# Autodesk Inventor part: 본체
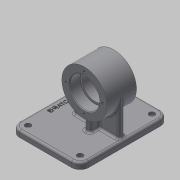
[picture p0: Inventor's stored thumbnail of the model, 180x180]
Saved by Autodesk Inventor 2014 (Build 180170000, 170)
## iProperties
Created: 2019-09
Part Number: 본체
Material: Generic
Document SubType Name: Modeling
Designer: kh
Density: 1 g/cm^3
Appearance: Default
Author: kh
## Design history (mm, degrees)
sketch "Sketch1"
  geometry: L1 (-51, -49)-(51, -49); L2 (63, -37)-(63, 37); L3 (51, 49)-(-51, 49); L4 (-63, 37)-(-63, -37); L5 (-63, -49)-(63, 49); L6 (63, -49)-(-63, 49); A1 r 12 centre (-51, 37) between (-51, 49) and (-63, 37); A2 r 12 centre (-51, -37) between (-63, -37) and (-51, -49); A3 r 12 centre (51, -37) between (51, -49) and (63, -37); A4 r 12 centre (51, 37) between (63, 37) and (51, 49); 1 further point
  constraints: 12 end point, 8 point on circle, 8 point on line, 8 tangent, 4 centre point, 3 equal radius, 2 midpoint, 2 parallel, 1 horizontal, 1 perpendicular
  dimensions: "d0" = 126 distance of L5.end L6.end; "d1" = 98 distance of L6.end L5.start; "d2" = 12 radius of A1
extrude "Extrusion1" new body sketch "Sketch1" distance "d3" = 9; taper "d4" = 0 deg
sketch "Sketch2"
  geometry: A1 r 12 centre (-51, 37) between (-51, 49) and (-63, 37) reference; A2 r 12 centre (51, 37) between (63, 37) and (51, 49) reference; A3 r 12 centre (51, -37) between (51, -49) and (63, -37) reference; A4 r 12 centre (-51, -37) between (-63, -37) and (-51, -49) reference; 5 further points
  constraints: 4 coincident
hole "Hole1" sketch "Sketch2" at (-51, 37), (51, 37), (-51, -37), (51, -37) diameter "d5" = 4.5; stored, may be unused: countersink angle "d9" = 90 deg, drill point angle "d11" = 118 deg; dims "d6" = 6, "d7" = 8, "d8" = 4.4, "d10" = 8
workplane "Work Plane3"
workplane "Work Plane4"
sketch "Sketch9"
  geometry: L1 (-12, -9)-(-12, 0) reference; L2 (-12, 0)-(114, 0) reference; L3 (114, 0)-(114, -9) reference; L4 (114, -9)-(-12, -9) reference; L5 (30, -91)-(72, -91); L6 (72, -91)-(72, -59); L7 (72, -59)-(30, -59); L8 (30, -59)-(30, -91); L9 (51, 0)-(51, -9); L10 (30, -80)-(45, -80); L11 (45, -80)-(45, -77); L12 (45, -77)-(57, -77); L13 (57, -77)-(57, -80); L14 (57, -80)-(72, -80)
  constraints: 20 end point, 4 parallel, 4 perpendicular, 2 point on line, 1 collinear, 1 horizontal, 1 midpoint, 2 other
  dimensions: "d52" = 64 diameter of L5 L7; "d53" = 59 vertical distance of L1.end L7.end; "d54" = 42 distance of L5.start L5.end; "d55" = 42 diameter of L10 L7; "d56" = 36 diameter of L12 L7; "d57" = 15 distance of L10.start L10.end
revolve "Revolution4" sketch "Sketch9" stored, may be unused: angle "d58" = 90 deg
sketch "Sketch10"
  geometry: C1 r 32 at (0, 0) reference; 2 further points
  constraints: 1 horizontal alignment
  dimensions: "d59" = 26 distance of point (26, 0) C1.centre
hole "Hole3" sketch "Sketch10" at (26, 0) diameter "d60" = 3.242; stored, may be unused: countersink angle "d64" = 90 deg, drill point angle "d66" = 118 deg; dims "d61" = 8, "d62" = 8, "d63" = 4.4, "d65" = 10
pattern_circular "Circular Pattern2" dims angle "d68" = 360 deg
mirror "Mirror2"
sketch "Sketch11"
  geometry: L1 (51, 49)-(-51, 49) reference; L2 (-51, -49)-(51, -49) reference; L3 (-4, 19)-(4, 19); L4 (4, 19)-(4, -45); L5 (4, -45)-(-4, -45); L6 (-4, -45)-(-4, 19); L7 (-17, -9)-(17, -9); L8 (17, -9)-(17, -17); L9 (17, -17)-(-17, -17); L10 (-17, -17)-(-17, -9); L11 (0, 0)-(0, 20.336); L12 (-17, -13)-(17, -13)
  constraints: 20 end point, 4 parallel, 3 perpendicular, 2 horizontal, 2 midpoint, 3 other
  dimensions: "d87" = 8 distance of L3.start L3.end; "d88" = 64 distance of L3.end L4.end; "d89" = 34 distance of L7.start L7.end; "d90" = 62 distance from line of L1 L12.end; "d91" = 8 distance of L9.end L7.start
fillet "Fillet1" dims "d83" = 0.3
chamfer "Chamfer1" distance "d84" = 1; stored, may be unused: second distance "d85" = 2, angle "d86" = 45 deg
extrude "Extrusion3" join sketch "Sketch11" stored distance "d92" = 9; taper "d93" = 0 deg
fillet "Fillet2" dims "d94" = 3
fillet "Fillet3" dims "d95" = 3
sketch "Sketch12"
  geometry: L1 (-20.739, 42.002)-(20.739, 42.002); L2 (20.739, 42.002)-(20.739, 35.998); L3 (20.739, 35.998)-(-20.739, 35.998); L4 (-20.739, 35.998)-(-20.739, 42.002); L5 (-20.739, 42.002)-(20.739, 35.998); L6 (-20.739, 35.998)-(20.739, 42.002); L7 (51, 49)-(-51, 49) reference; L8 (63, -37)-(63, 37) reference; 2 further points
  constraints: 4 end point, 1 midpoint, 2 other
  dimensions: "d100" = 10 distance from line of L7 point (0, 39); "d101" = 63 distance from line of L8 point (0, 39)
emboss "Emboss1" sketch "Sketch12" dims "d0" = 126, "d1" = 98, "d2" = 12, "d98" = 0.5, "d99" = 0
body "Solid1"
node "Project Cut Edges5"
other parameters: "d42" = 28, "d51" = -62
